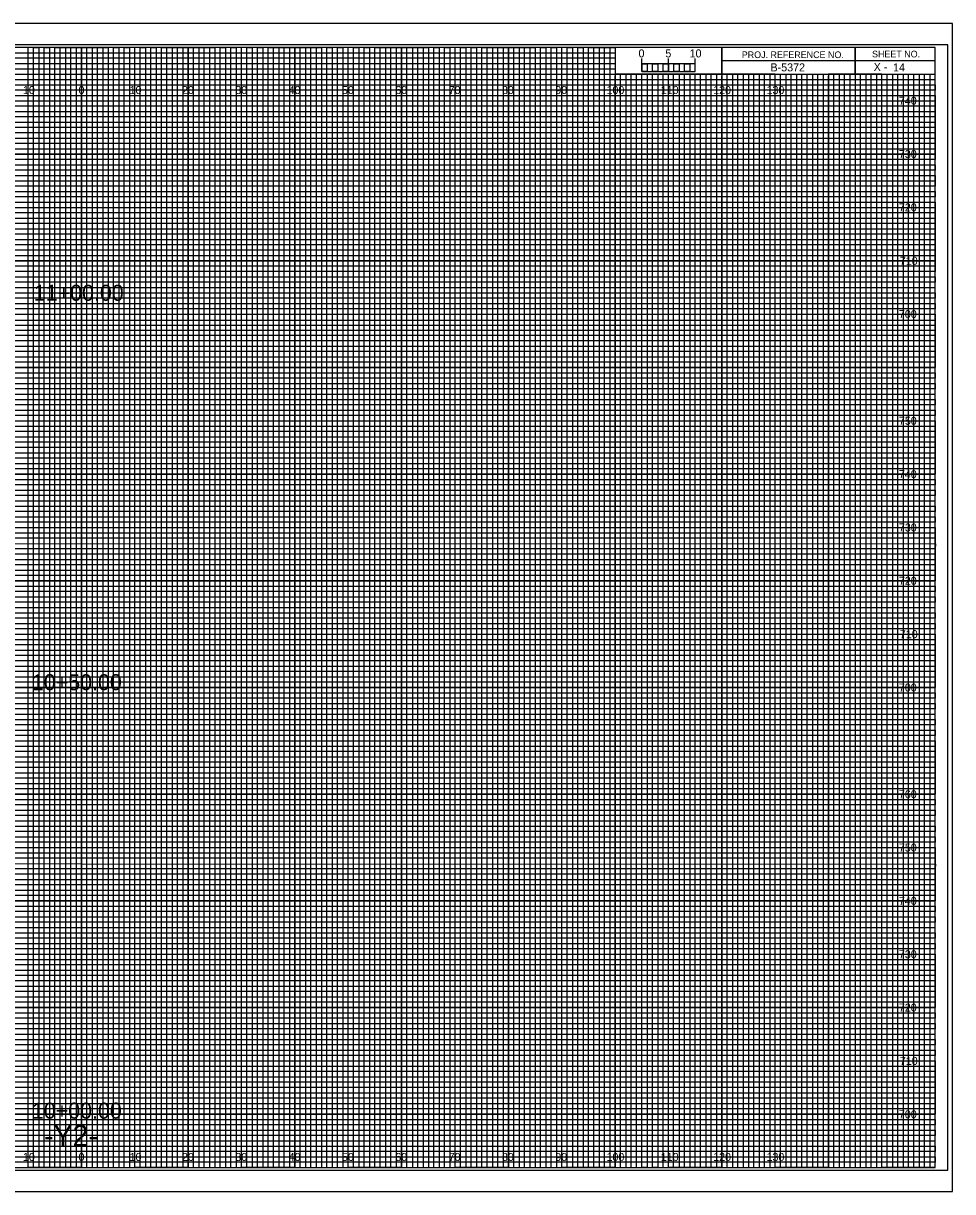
# Model space of a CAD drawing. Extents: x -13 to 323, y -5 to 534.
# Drawn here: x 149.1 to 323.3, y -4.5 to 214.5 of the extents above; entities that cross this region are included whole.
import ezdxf

# ---------------------------------------------------------------- set-up
doc = ezdxf.new("R2010")
doc.units = 0
for name, color, linetype in [('Prop XS Alignment Label', 7, 'Continuous'), ('Prop XS Bar Scale Labels', 7, 'Continuous'), ('Prop XS Elevation Labels', 7, 'Continuous'), ('Prop XS Offset Labels', 7, 'Continuous'), ('Prop XS Project Number', 7, 'Continuous'), ('Prop XS Sheet Number', 7, 'Continuous'), ('Prop XS Station Labels', 7, 'Continuous'), ('Sheet Cross Section CELL', 7, 'Continuous'), ('Sheet Cross Section Grid Major CELL', 7, 'Continuous'), ('Sheet Cross Section Grid Middle CELL', 7, 'Continuous'), ('Sheet Cross Section Grid Minor 1 CELL', 7, 'Continuous'), ('Sheet Cross Section Grid Minor 2 CELL', 7, 'Continuous'), ('Sheet Cross Section Scale CELL', 7, 'Continuous'), ('Sheet Cutting Line CELL', 7, 'Continuous'), ('Sheet DOT Grid CELL', 7, 'Continuous'), ('Sheet Plot Border Inside CELL', 7, 'Continuous'), ('Sheet Plot Border Outside CELL', 7, 'Continuous')]:
    doc.layers.add(name, color=color, linetype=linetype)

msp = doc.modelspace()

# ---------------------------------------------------------------- linework, layer by layer
at = {"layer": 'Sheet Cross Section CELL'}
for p, q in [((305, 210), (305, 205)), ((305, 205), (305, 210)), ((280, 207.5), (280, 205)), ((320, 207.49), (280, 207.49)), ((280, 205), (320, 205))]:
    msp.add_line(p, q, dxfattribs=at)
for points in [[(320, 210), (0, 210), (0, 0), (320, 0)], [(280, 210), (260, 210), (260, 205.03), (280, 205.03)], [(320, 210), (280, 210), (280, 205), (320, 205)]]:
    msp.add_lwpolyline(points, close=True, dxfattribs=at)
at = {"layer": 'Sheet Cross Section Grid Major CELL'}
for p, q in [((150, 210), (140, 210)), ((150, 0), (150, 210)), ((170, 210), (160, 210)), ((160, 210), (160, 0)), ((170, 0), (170, 210)), ((190, 210), (180, 210)), ((180, 210), (180, 0)), ((190, 0), (190, 210)), ((210, 210), (200, 210)), ((200, 210), (200, 0)), ((210, 0), (210, 210)), ((230, 210), (220, 210)), ((220, 210), (220, 0)), ((230, 0), (230, 210)), ((250, 210), (240, 210)), ((240, 210), (240, 0)), ((250, 0), (250, 210)), ((260, 210), (260, 0)), ((270, 0), (270, 205)), ((290, 205), (280, 205)), ((280, 205), (280, 0)), ((290, 0), (290, 205)), ((310, 205), (300, 205)), ((300, 205), (300, 0)), ((310, 0), (310, 205)), ((160, 0), (150, 0)), ((180, 0), (170, 0)), ((200, 0), (190, 0)), ((220, 0), (210, 0)), ((240, 0), (230, 0)), ((260, 0), (250, 0)), ((280, 0), (270, 0)), ((300, 0), (290, 0)), ((320, 0), (310, 0)), ((320, 0), (320, 0))]:
    msp.add_line(p, q, dxfattribs=at)
for points in [[(0, 200), (320, 200), (320, 190), (0, 190)], [(0, 180), (320, 180), (320, 170), (0, 170)], [(0, 160), (320, 160), (320, 150), (0, 150)], [(0, 140), (320, 140), (320, 130), (0, 130)], [(0, 120), (320, 120), (320, 110), (0, 110)], [(0, 100), (320, 100), (320, 90), (0, 90)], [(0, 80), (320, 80), (320, 70), (0, 70)], [(0, 60), (320, 60), (320, 50), (0, 50)], [(0, 40), (320, 40), (320, 30), (0, 30)], [(0, 20), (320, 20), (320, 10), (0, 10)]]:
    msp.add_lwpolyline(points, dxfattribs=at)
at = {"layer": 'Sheet Cross Section Grid Middle CELL'}
for points in [[(145, 0), (155, 0), (155, 210), (165, 210), (165, 0), (175, 0), (175, 210), (185, 210), (185, 0), (195, 0), (195, 210), (205, 210), (205, 0), (215, 0), (215, 210), (225, 210), (225, 0), (235, 0), (235, 210), (245, 210), (245, 0), (255, 0), (255, 210), (259.93, 210), (260, 210), (260, 205), (264.99, 205), (264.99, 0), (275, 0), (275, 205), (285, 205), (285, 0), (295, 0), (295, 205), (305, 205), (305, 0), (315, 0), (315, 205)], [(0, 205), (275, 205)], [(0, 185), (320, 185), (320, 195), (0, 195)], [(0, 165), (320, 165), (320, 175), (0, 175)], [(0, 145), (320, 145), (320, 155), (0, 155)], [(0, 125), (320, 125), (320, 135), (0, 135)], [(0, 105), (320, 105), (320, 115), (0, 115)], [(0, 85), (320, 85), (320, 95), (0, 95)], [(0, 65), (320, 65), (320, 75), (0, 75)], [(0, 45), (320, 45), (320, 55), (0, 55)], [(0, 25), (320, 25), (320, 35), (0, 35)], [(0, 5), (320, 5), (320, 15), (0, 15)]]:
    msp.add_lwpolyline(points, dxfattribs=at)
at = {"layer": 'Sheet Cross Section Grid Minor 1 CELL'}
for p, q in [((0, 209), (260, 209)), ((260, 209), (260, 207.98)), ((260, 207.98), (0, 207.98)), ((0, 207), (260, 207)), ((260, 205.89), (0, 205.89)), ((260, 207), (260, 205.89)), ((0, 204), (320, 204))]:
    msp.add_line(p, q, dxfattribs=at)
for points in [[(0, 203), (270, 203), (320, 203), (320, 202), (0, 202)], [(0, 201), (320, 201), (320, 199), (0, 199)], [(0, 198), (320, 198), (320, 197), (0, 196.98)], [(0, 196), (320, 196), (320, 194), (0, 194)], [(0, 193), (320, 193), (320, 192), (0, 192)], [(0, 191), (320, 191), (320, 189), (0, 189)], [(0, 188), (320, 188), (320, 187), (0, 187)], [(0, 186), (320, 186), (320, 184), (0, 184)], [(0, 183), (320, 183), (320, 182), (0, 182)], [(0, 181), (320, 181), (320, 179), (0, 179)], [(0, 178), (320, 178), (320, 177), (0, 177)], [(0, 176), (320, 176), (320, 173.95), (320, 173), (320, 172), (0, 172)], [(0, 174), (320, 174), (320, 173), (0, 173)], [(0, 171), (320, 171), (320, 169), (0, 169.03)], [(0, 169.03), (320, 169), (320, 168), (0, 168)], [(0, 167), (320, 167), (320, 166), (0, 166)], [(0, 164), (320, 164), (320, 163), (0, 163)], [(0, 162), (320, 162), (320, 161), (0, 161)], [(-0.07, 158.89), (320, 158.89), (320, 157.88), (-0.07, 157.88)], [(0, 157), (320, 157), (320, 156), (0, 156)], [(0, 154), (320, 154), (320, 153), (0, 153)], [(0, 152), (320, 152), (320, 151), (0, 151)], [(0, 149), (320, 149), (320, 148), (0, 148)], [(0, 147), (320, 147), (320, 146), (0, 146)], [(0, 144), (320, 144), (320, 143), (0, 143)], [(0, 142), (320, 142), (320, 141), (0, 141)], [(0, 139), (320, 139), (319.99, 137.98), (0, 138)], [(0, 137), (320, 137), (320, 136), (0, 136)], [(0, 134), (320, 134), (320, 133), (0, 133)], [(0, 132), (320, 132), (320, 131), (0, 131)], [(0, 129), (320, 129), (320, 128), (0, 128)], [(0, 127), (320, 127), (320, 126), (0, 126)], [(0, 124), (320, 124), (320, 123), (0, 123)], [(0, 122), (320, 122), (320, 121), (0, 121)], [(0, 119), (320, 119), (320, 118), (0, 118)], [(0, 116.99), (320.07, 116.91), (320, 116), (0, 116)], [(0, 114), (320, 114), (320, 113), (0, 113)], [(0, 112), (320, 112), (320, 111), (0, 111)], [(0, 109), (320, 109), (320, 108), (0, 108)], [(0, 107), (320, 107), (320, 106), (0, 106)], [(0, 104), (320, 104), (320, 103), (0, 103)], [(0, 102), (320, 102), (320, 101), (0, 101)], [(0, 99), (320, 99), (320, 98), (0, 98)], [(0, 97), (320, 97), (320, 96), (0, 96)], [(0, 94), (320, 94), (320, 93), (0, 93)], [(0, 92), (320, 92), (320, 91), (0, 91)], [(0, 89), (320, 89), (320, 88), (0, 88)], [(0, 87), (320, 87), (320, 86), (0, 86)], [(0, 84), (320, 84), (320, 83), (0, 83)], [(0, 82), (320, 82), (320, 81), (0, 81)], [(0, 79), (320, 79), (319.99, 77.98), (0, 78)], [(0, 77), (320, 77), (320, 76), (0, 76)], [(0, 74), (320, 74), (320, 73), (0, 73)], [(0, 72), (320, 72), (320, 71), (0, 71)], [(0, 69), (320, 69), (320, 68), (0, 68)], [(0, 67), (320, 67), (320, 66), (0, 66)], [(0, 64), (320, 64), (320, 63), (0, 63)], [(0, 62), (320, 62), (320, 61), (0, 61)], [(0, 59), (320, 59), (320, 58), (0, 58)], [(0, 56.99), (320.07, 56.91), (320, 56), (0, 56)], [(0, 54), (320, 54), (320, 53), (0, 53)], [(0, 52), (320, 52), (320, 51), (0, 51)], [(0, 49), (320, 49), (320, 48), (0, 48)], [(0, 47), (320, 47), (320, 46), (0, 46)], [(0, 44), (320, 44), (320, 43), (0, 43)], [(0, 42), (320, 42), (320, 41), (0, 41)], [(0, 39), (320, 39), (320, 38), (0, 38)], [(0, 37), (320, 37), (320, 36), (0, 36)], [(0, 34), (320, 34), (320, 33), (0, 33)], [(0, 32), (320, 32), (320, 31), (0, 31)], [(0, 29), (320, 29), (320, 28), (0, 28)], [(0, 27), (320, 27), (320, 26), (0, 26)], [(0, 24), (320, 24), (320, 23), (0, 23)], [(0, 22), (320, 22), (320, 21), (0, 21)], [(0, 19), (320, 19), (320, 18), (0, 18)], [(0, 17), (320, 17), (320, 16), (0, 16)], [(0, 14), (320, 14), (320, 13), (0, 13)], [(0, 12), (320, 12), (320, 11), (0, 11)], [(0, 9), (320, 9), (320, 8), (0, 8)], [(0, 7), (320, 7), (320, 6), (0, 6)], [(0, 4), (320, 4), (320, 3), (0, 3)], [(0, 2), (320, 2), (320, 1), (0, 1)]]:
    msp.add_lwpolyline(points, dxfattribs=at)
at = {"layer": 'Sheet Cross Section Grid Minor 2 CELL'}
for p, q in [((267, 205), (266.01, 205)), ((266.01, 205), (266.01, 0)), ((267, 0), (267, 205)), ((269, 205), (268, 205)), ((268, 205), (268, 0)), ((269, 0), (269, 205)), ((266.01, 0), (265, 0)), ((268, 0), (267, 0))]:
    msp.add_line(p, q, dxfattribs=at)
for points in [[(150, 0), (151, 0), (151, 210), (152, 210), (152, 0)], [(152, 0), (153, 0), (153, 210), (154, 210), (154, 0)], [(155, 0), (156, 0), (156, 210), (157, 210), (157, 0)], [(157, 0), (158, 0), (158, 210), (159, 210), (159, 0)], [(160, 0), (161, 0), (161, 210), (162, 210), (162, 0)], [(162, 0), (163, 0), (163, 210), (164, 210), (164, 0)], [(165, 0), (166, 0), (166, 210), (167, 210), (167, 0)], [(167, 0), (168, 0), (168, 210), (169, 210), (169, 0)], [(170, 0), (171, 0), (171, 210), (172, 210), (172, 0)], [(172, 0), (173, 0), (173, 210), (174, 210), (174, 0)], [(175, 0), (176, 0), (176, 210), (177, 210), (177, 0)], [(177, 0), (178, 0), (178, 210), (179, 210), (179, 0)], [(180, 0), (181, 0), (181, 210), (182, 210), (182, 0)], [(182, 0), (183, 0), (183, 210), (184, 210), (184, 0)], [(185, 0), (186, 0), (186, 210), (187, 210), (187, 0)], [(187, 0), (188, 0), (188, 210), (189, 210), (189, 0)], [(190, 0), (191, 0), (191, 210), (192, 210), (192, 0)], [(192, 0), (193, 0), (193, 210), (194, 210), (194, 0)], [(195, 0), (196, 0), (196, 210), (197, 210), (197, 0)], [(197, 0), (198, 0), (198, 210), (199, 210), (199, 0)], [(200, 0), (201, 0), (201, 210), (202, 210), (202, 0)], [(202, 0), (203, 0), (203, 210), (204, 210), (204, 0)], [(205, 0), (206, 0), (206, 210), (207, 210), (207, 0)], [(207, 0), (208, 0), (208, 210), (209, 210), (209, 0)], [(210, 0), (211, 0), (211, 210), (212, 210), (212, 0)], [(212, 0), (213, 0), (213, 210), (214, 210), (214, 0)], [(215, 0), (216, 0), (216, 210), (217, 210), (217, 0)], [(217, 0), (218, 0), (218, 210), (219, 210), (219, 0)], [(220, 0), (221, 0), (221, 210), (222, 210), (222, 0)], [(222, 0), (223, 0), (223, 210), (224, 210), (224, 0)], [(225, 0), (226, 0), (226, 210), (227, 210), (227, 0)], [(227, 0), (228, 0), (228, 210), (229, 210), (229, 0)], [(230, 0), (231, 0), (231, 210), (232, 210), (232, 0)], [(232, 0), (233, 0), (233, 210), (234, 210), (234, 0)], [(235, 0), (236, 0), (236, 210), (237, 210), (237, 0)], [(237, 0), (238, 0), (238, 210), (239, 210), (239, 0)], [(240, 0), (241, 0), (241, 210), (242, 210), (242, 0)], [(242, 0), (243, 0), (243, 210), (244, 210), (244, 0)], [(245, 0), (246, 0), (246, 210), (247, 210), (247, 0)], [(247, 0), (248, 0), (248, 210), (249, 210), (249, 0)], [(250, 0), (251, 0), (251, 210), (252, 210), (252, 0)], [(252, 0), (253, 0), (253, 210), (254, 210), (254, 0)], [(255, 0), (256, 0), (256, 210), (257, 210), (257, 0)], [(257, 0), (258, 0), (258, 210), (259, 210), (259, 0)], [(260, 0), (261, 0), (261, 205), (262.02, 205), (262.02, 0)], [(262, 0), (263, 0), (263, 205), (263.99, 205), (263.99, 0)], [(270, 0), (270.98, 0), (270.98, 205), (272, 205), (272, 0)], [(272, 0), (273, 0), (273, 205), (274.05, 205), (274.05, 0)], [(275, 0), (276, 0), (276, 205), (277, 205), (277, 0)], [(277, 0), (278, 0), (278, 205), (279, 205), (279, 0)], [(280, 0), (281, 0), (281, 205), (282, 205), (282, 0)], [(282, 0), (283, 0), (283, 205), (284, 205), (284, 0)], [(285, 0), (286, 0), (286, 205), (287, 205), (287, 0)], [(287, 0), (288, 0), (288, 205), (289, 205), (289, 0)], [(290, 0), (291, 0), (291, 205), (292, 205), (292, 0)], [(292, 0), (293, 0), (293, 205), (294, 205), (294, 0)], [(295, 0), (296, 0), (296, 205), (297, 205), (297, 0)], [(297, 0), (298, 0), (298, 205), (299, 205), (299, 0)], [(300, 0), (301, 0), (301, 205), (302, 205), (302, 0)], [(302, 0), (303, 0), (303, 205), (304, 205), (304, 0)], [(305, 0), (306, 0), (306, 205), (307, 205), (307, 0)], [(307, 0), (308, 0), (308, 205), (309, 205), (309, 0)], [(310, 0), (311, 0), (311, 205), (312, 205), (312, 0)], [(312, 0), (313, 0), (313, 205), (314, 205), (314, 0)], [(315, 0), (316, 0), (316, 205), (317, 205), (317, 0)], [(317, 0), (318, 0), (318, 205), (319, 205), (319, 0)]]:
    msp.add_lwpolyline(points, dxfattribs=at)
at = {"layer": 'Sheet Cross Section Scale CELL'}
for p, q in [((265, 205.49), (265, 207.9)), ((265, 206.9), (265, 207.9)), ((270, 205.49), (270, 207.9)), ((275, 205.49), (275, 207.9)), ((275, 206.9), (275, 207.9))]:
    msp.add_line(p, q, dxfattribs=at)
for points in [[(275, 206.9), (265, 206.9), (265, 205.49), (275, 205.49)], [(265, 206.9), (266, 206.9), (266, 205.49), (265, 205.49)], [(267, 206.9), (268, 206.9), (268, 205.49), (267, 205.49)], [(269, 206.9), (270, 206.9), (270, 205.49), (269, 205.49)], [(271, 206.9), (272, 206.9), (272, 205.49), (271, 205.49)], [(273, 206.9), (274, 206.9), (274, 205.49), (273, 205.49)]]:
    msp.add_lwpolyline(points, close=True, dxfattribs=at)
at = {"layer": 'Sheet Cutting Line CELL'}
for p, q in [((323.3, 214.5), (-13.4, 214.5)), ((-13.4, -4.5), (323.3, -4.5))]:
    msp.add_line(p, q, dxfattribs=at)
at = {"layer": 'Sheet DOT Grid CELL'}
for p, q in [((150, 0), (150, 210)), ((160, 0), (160, 210)), ((170, 0), (170, 210)), ((180, 0), (180, 210)), ((190, 0), (190, 210)), ((200, 0), (200, 210)), ((210, 0), (210, 210)), ((220, 0), (220, 210)), ((230, 0), (230, 210)), ((240, 0), (240, 210)), ((250, 0), (250, 210)), ((260, 0), (260, 204.69)), ((270, 0), (270, 204.69)), ((280, 0), (280, 204.69)), ((290, 0), (290, 204.69)), ((300, 0), (300, 204.69)), ((310, 0), (310, 204.69)), ((0, 200), (320, 200)), ((0, 190), (320, 190)), ((0, 180), (320, 180)), ((0, 170), (320, 170)), ((0, 160), (320, 160)), ((0, 150), (320, 150)), ((0, 140), (320, 140)), ((0, 130), (320, 130)), ((0, 120), (320, 120)), ((0, 110), (320, 110)), ((0, 100), (320, 100)), ((0, 90), (320, 90)), ((0, 80), (320, 80)), ((0, 70), (320, 70)), ((0, 60), (320, 60)), ((0, 50), (320, 50)), ((0, 40), (320, 40)), ((0, 30), (320, 30)), ((0, 20), (320, 20)), ((0, 10), (320, 10))]:
    msp.add_line(p, q, dxfattribs=at)
at = {"layer": 'Sheet Plot Border Inside CELL'}
msp.add_lwpolyline([(-10.8, -0.5), (322.4, -0.5), (322.4, 210.5), (-10.8, 210.5)], close=True, dxfattribs=at)
at = {"layer": 'Sheet Plot Border Outside CELL'}
msp.add_lwpolyline([(-13.4, -4.5), (323.3, -4.5), (323.3, 214.5), (-13.4, 214.5)], close=True, dxfattribs=at)

# ---------------------------------------------------------------- texts
at = {"layer": 'Prop XS Alignment Label'}
msp.add_text('-Y2-', height=4, dxfattribs=at).set_placement((152.94, 4))
at = {"layer": 'Prop XS Bar Scale Labels'}
for s, p in [('5', (269.44, 208.12)), ('10', (273.99, 208.12))]:
    msp.add_text(s, height=1.5, dxfattribs=at).set_placement(p)
at = {"layer": 'Prop XS Elevation Labels'}
for s, p in [('740', (313.22, 199.25)), ('730', (313.22, 189.25)), ('720', (313.22, 179.25)), ('710', (313.4, 169.25)), ('700', (313.22, 159.25)), ('750', (313.22, 139.25)), ('740', (313.22, 129.25)), ('730', (313.22, 119.25)), ('720', (313.22, 109.25)), ('710', (313.4, 99.25)), ('700', (313.22, 89.25)), ('760', (313.22, 69.25)), ('750', (313.22, 59.25)), ('740', (313.22, 49.25)), ('730', (313.22, 39.25)), ('720', (313.22, 29.25)), ('710', (313.4, 19.25)), ('700', (313.22, 9.25))]:
    msp.add_text(s, height=1.5, dxfattribs=at).set_placement(p)
at = {"layer": 'Prop XS Offset Labels'}
for s, p in [('10', (148.99, 201.25)), ('0', (159.41, 201.25)), ('10', (168.99, 201.25)), ('20', (178.81, 201.25)), ('30', (188.81, 201.25)), ('40', (198.81, 201.25)), ('50', (208.81, 201.25)), ('60', (218.81, 201.25)), ('70', (228.81, 201.25)), ('80', (238.81, 201.25)), ('90', (248.81, 201.25)), ('100', (258.4, 201.25)), ('110', (268.58, 201.25)), ('120', (278.4, 201.25)), ('130', (288.4, 201.25)), ('10', (148.99, 1.25)), ('0', (159.41, 1.25)), ('10', (168.99, 1.25)), ('20', (178.81, 1.25)), ('30', (188.81, 1.25)), ('40', (198.81, 1.25)), ('50', (208.81, 1.25)), ('60', (218.81, 1.25)), ('70', (228.81, 1.25)), ('80', (238.81, 1.25)), ('90', (248.81, 1.25)), ('100', (258.4, 1.25)), ('110', (268.58, 1.25)), ('120', (278.4, 1.25)), ('130', (288.4, 1.25))]:
    msp.add_text(s, height=1.5, dxfattribs=at).set_placement(p)
at = {"layer": 'Prop XS Project Number'}
msp.add_text('B-5372', height=1.5, dxfattribs=at).set_placement((289.15, 205.5))
at = {"layer": 'Prop XS Sheet Number'}
msp.add_text('14', height=1.5, dxfattribs=at).set_placement((312.13, 205.5))
at = {"layer": 'Prop XS Station Labels'}
for s, p in [('11+00.00', (151.04, 162.5)), ('10+50.00', (150.68, 89.5)), ('10+00.00', (150.68, 9.18))]:
    msp.add_text(s, height=3, dxfattribs=at).set_placement(p)
at = {"layer": 'Sheet Cross Section CELL'}
for s, height, p in [('PROJ. REFERENCE NO.', 1.25, (283.77, 207.99)), ('SHEET NO.', 1.25, (308.19, 208.12)), ('X -    ', 1.5, (308.5, 205.58))]:
    msp.add_text(s, height=height, dxfattribs=at).set_placement(p)
at = {"layer": 'Sheet Cross Section Scale CELL'}
msp.add_text('0', height=1.5, dxfattribs=at).set_placement((264.41, 208.12))

doc.saveas('drawing.dxf')
